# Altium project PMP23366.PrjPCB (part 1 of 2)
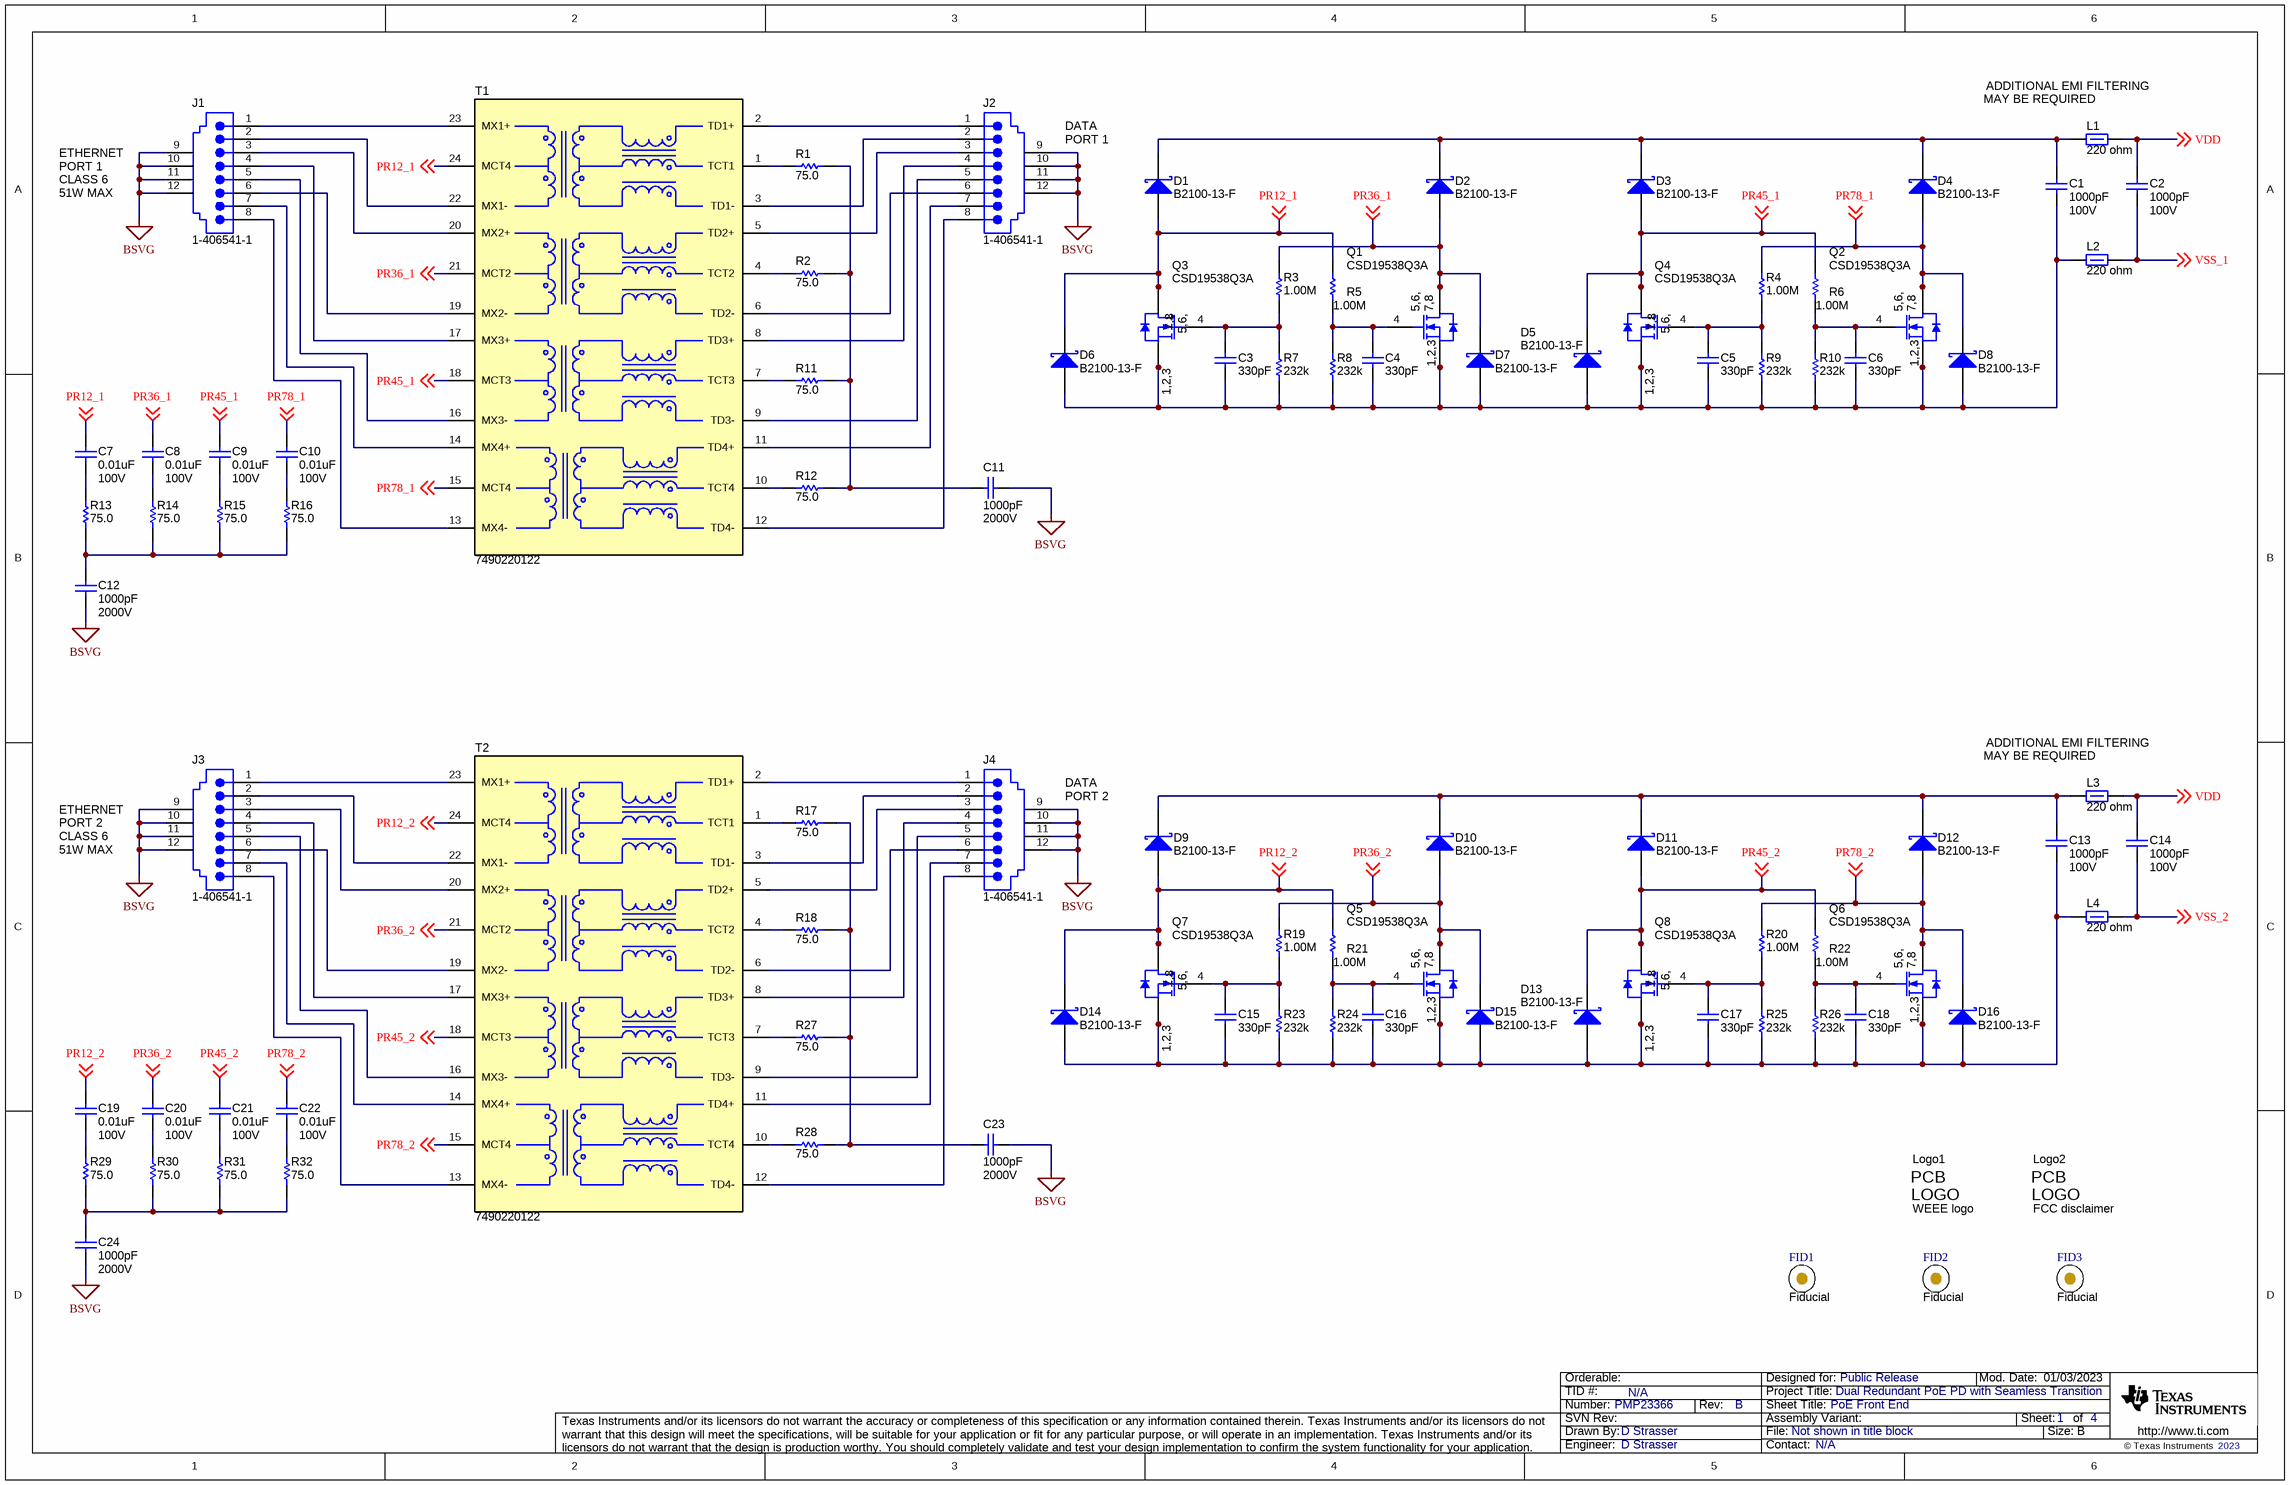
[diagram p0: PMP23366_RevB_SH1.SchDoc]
CopyrightYear: 2023; PCB_Layout: D Strasser; PCB_Rev: B; PRJ_Customer: Public Release; PRJ_Engineer: D Strasser; PRJ_Number: PMP23366; PRJ_Title: Dual Redundant PoE PD with Seamless Transition; SCH_Rev: B; TechSupport: N/A; TID: N/A
4 sheets, 370 parts. Net scope: global (net labels, ports and power ports of the same name join across sheets).
Board file: PMP23366_RevB.PcbDoc
Sheets:
  PMP23366_RevB_SH1.SchDoc
  PMP23366_RevB_SH2.SchDoc
  PMP23366_RevB_SH3.SchDoc
  PMP23366_RevB_SH4.SchDoc

## Sheet PMP23366_RevB_SH1.SchDoc: PoE Front End
size 431 x 279 mm; Date: Not shown in title block; ApprovedBy: Not shown in title block; CheckedBy: Not shown in title block; Author: Not shown in title block; CompanyName: Not shown in title block; DrawnBy: D Strasser; Engineer: Not shown in title block; Organization: Not shown in title block; Address1: Not shown in title block; Address2: Not shown in title block; Address3: Not shown in title block; Address4: Not shown in title block; DocumentNumber: 1; Revision: Use project parameter SCH_Rev; SheetNumber: 1; SheetTotal: 4; PageSetup: Record=PageOptions¦CenterHorizontal=True¦CenterVertical=True¦PrintScale=1.00¦XCorrection=1.00¦YCorrection=1.00¦PrintKind=0¦BorderSize=5000000¦LeftOffset=0¦BottomOffset=0¦Orientation=2¦PaperLength=1000¦PaperWidth=1000¦Scale=100¦PaperSource=15¦PrintQuality=600¦MediaType=1¦DitherType=10¦PaperKind=Letter¦PrintScaleMode=1

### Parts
C1  ValueDisplayed: 1000pF  Value2: 100V  [0603_HV]  (hidden comment: Capacitor)
C2  ValueDisplayed: 1000pF  Value2: 100V  [0603_HV]  (hidden comment: Capacitor)
C3  ValueDisplayed: 330pF  [0603L]  (hidden comment: Capacitor)
C4  ValueDisplayed: 330pF  [0603L]  (hidden comment: Capacitor)
C5  ValueDisplayed: 330pF  [0603L]  (hidden comment: Capacitor)
C6  ValueDisplayed: 330pF  [0603L]  (hidden comment: Capacitor)
C7  ValueDisplayed: 0.01uF  Value2: 100V  [0603L]  (hidden comment: Capacitor)
C8  ValueDisplayed: 0.01uF  Value2: 100V  [0603L]  (hidden comment: Capacitor)
C9  ValueDisplayed: 0.01uF  Value2: 100V  [0603L]  (hidden comment: Capacitor)
C10  ValueDisplayed: 0.01uF  Value2: 100V  [0603L]  (hidden comment: Capacitor)
C11  ValueDisplayed: 1000pF  Value2: 2000V  [1812]  (hidden comment: Capacitor)
C12  ValueDisplayed: 1000pF  Value2: 2000V  [1812]  (hidden comment: Capacitor)
C13  ValueDisplayed: 1000pF  Value2: 100V  [0603_HV]  (hidden comment: Capacitor)
C14  ValueDisplayed: 1000pF  Value2: 100V  [0603_HV]  (hidden comment: Capacitor)
C15  ValueDisplayed: 330pF  [0603L]  (hidden comment: Capacitor)
C16  ValueDisplayed: 330pF  [0603L]  (hidden comment: Capacitor)
C17  ValueDisplayed: 330pF  [0603L]  (hidden comment: Capacitor)
C18  ValueDisplayed: 330pF  [0603L]  (hidden comment: Capacitor)
C19  ValueDisplayed: 0.01uF  Value2: 100V  [0603L]  (hidden comment: Capacitor)
C20  ValueDisplayed: 0.01uF  Value2: 100V  [0603L]  (hidden comment: Capacitor)
C21  ValueDisplayed: 0.01uF  Value2: 100V  [0603L]  (hidden comment: Capacitor)
C22  ValueDisplayed: 0.01uF  Value2: 100V  [0603L]  (hidden comment: Capacitor)
C23  ValueDisplayed: 1000pF  Value2: 2000V  [1812]  (hidden comment: Capacitor)
C24  ValueDisplayed: 1000pF  Value2: 2000V  [1812]  (hidden comment: Capacitor)
D1  B2100-13-F  [SMB]
D2  B2100-13-F  [SMB]
D3  B2100-13-F  [SMB]
D4  B2100-13-F  [SMB]
D5  B2100-13-F  [SMB]
D6  B2100-13-F  [SMB]
D7  B2100-13-F  [SMB]
D8  B2100-13-F  [SMB]
D9  B2100-13-F  [SMB]
D10  B2100-13-F  [SMB]
D11  B2100-13-F  [SMB]
D12  B2100-13-F  [SMB]
D13  B2100-13-F  [SMB]
D14  B2100-13-F  [SMB]
D15  B2100-13-F  [SMB]
D16  B2100-13-F  [SMB]
FID1  Fiducial  [Fiducial10-20]
FID2  Fiducial  [Fiducial10-20]
FID3  Fiducial  [Fiducial10-20]
J1  1-406541-1  [TEC_1-406541-1]
J2  1-406541-1  [TEC_1-406541-1]
J3  1-406541-1  [TEC_1-406541-1]
J4  1-406541-1  [TEC_1-406541-1]
L1  value 220 ohm  [0603_HV]  (hidden comment: Ferrite_Bead)
L2  value 220 ohm  [0603_HV]  (hidden comment: Ferrite_Bead)
L3  value 220 ohm  [0603_HV]  (hidden comment: Ferrite_Bead)
L4  value 220 ohm  [0603_HV]  (hidden comment: Ferrite_Bead)
Logo1  WEEE logo  [WEEE_Minimum]  (no BOM)
Logo2  FCC disclaimer  [FCC_disclaimer]  (no BOM)
Q1  CSD19538Q3A  [DNH0008A_NV]
Q2  CSD19538Q3A  [DNH0008A_NV]
Q3  CSD19538Q3A  [DNH0008A_NV]
Q4  CSD19538Q3A  [DNH0008A_NV]
Q5  CSD19538Q3A  [DNH0008A_NV]
Q6  CSD19538Q3A  [DNH0008A_NV]
Q7  CSD19538Q3A  [DNH0008A_NV]
Q8  CSD19538Q3A  [DNH0008A_NV]
R1  value 75.0  [0603L]  (hidden comment: Resistor)
R2  value 75.0  [0603L]  (hidden comment: Resistor)
R3  ValueDisplayed: 1.00M  [0603L]  (hidden comment: Resistor)
R4  ValueDisplayed: 1.00M  [0603L]  (hidden comment: Resistor)
R5  ValueDisplayed: 1.00M  [0603L]  (hidden comment: Resistor)
R6  ValueDisplayed: 1.00M  [0603L]  (hidden comment: Resistor)
R7  ValueDisplayed: 232k  [0603L]  (hidden comment: Resistor)
R8  ValueDisplayed: 232k  [0603L]  (hidden comment: Resistor)
R9  ValueDisplayed: 232k  [0603L]  (hidden comment: Resistor)
R10  ValueDisplayed: 232k  [0603L]  (hidden comment: Resistor)
R11  value 75.0  [0603L]  (hidden comment: Resistor)
R12  value 75.0  [0603L]  (hidden comment: Resistor)
R13  value 75.0  [0603L]  (hidden comment: Resistor)
R14  value 75.0  [0603L]  (hidden comment: Resistor)
R15  value 75.0  [0603L]  (hidden comment: Resistor)
R16  value 75.0  [0603L]  (hidden comment: Resistor)
R17  value 75.0  [0603L]  (hidden comment: Resistor)
R18  value 75.0  [0603L]  (hidden comment: Resistor)
R19  ValueDisplayed: 1.00M  [0603L]  (hidden comment: Resistor)
R20  ValueDisplayed: 1.00M  [0603L]  (hidden comment: Resistor)
R21  ValueDisplayed: 1.00M  [0603L]  (hidden comment: Resistor)
R22  ValueDisplayed: 1.00M  [0603L]  (hidden comment: Resistor)
R23  ValueDisplayed: 232k  [0603L]  (hidden comment: Resistor)
R24  ValueDisplayed: 232k  [0603L]  (hidden comment: Resistor)
R25  ValueDisplayed: 232k  [0603L]  (hidden comment: Resistor)
R26  ValueDisplayed: 232k  [0603L]  (hidden comment: Resistor)
R27  value 75.0  [0603L]  (hidden comment: Resistor)
R28  value 75.0  [0603L]  (hidden comment: Resistor)
R29  value 75.0  [0603L]  (hidden comment: Resistor)
R30  value 75.0  [0603L]  (hidden comment: Resistor)
R31  value 75.0  [0603L]  (hidden comment: Resistor)
R32  value 75.0  [0603L]  (hidden comment: Resistor)
T1  7490220122  [Wurth_7490220122]
T2  7490220122  [Wurth_7490220122]

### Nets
BSVG: C11.1 C12.2 C23.1 C24.2 J1.9 J1.10 J1.11 J1.12 J2.9 J2.10 J2.11 J2.12 J3.9 J3.10 J3.11 J3.12 J4.9 J4.10 J4.11 J4.12
PR12_1: C7.1 D1.2(A) D6.1(K) Q3.5(D) Q3.6(D) Q3.7(D) Q3.8(D) Q3.9(D) R5.1 T1.24(MCT4) ; off-sheet PR12_1
PR12_2: C19.1 D9.2(A) D14.1(K) Q7.5(D) Q7.6(D) Q7.7(D) Q7.8(D) Q7.9(D) R21.1 T2.24(MCT4) ; off-sheet PR12_2
PR36_1: C8.1 D2.2(A) D7.1(K) Q1.5(D) Q1.6(D) Q1.7(D) Q1.8(D) Q1.9(D) R3.1 T1.21(MCT2) ; off-sheet PR36_1
PR36_2: C20.1 D10.2(A) D15.1(K) Q5.5(D) Q5.6(D) Q5.7(D) Q5.8(D) Q5.9(D) R19.1 T2.21(MCT2) ; off-sheet PR36_2
PR45_1: C9.1 D3.2(A) D5.1(K) Q4.5(D) Q4.6(D) Q4.7(D) Q4.8(D) Q4.9(D) R6.1 T1.18(MCT3) ; off-sheet PR45_1
PR45_2: C21.1 D11.2(A) D13.1(K) Q8.5(D) Q8.6(D) Q8.7(D) Q8.8(D) Q8.9(D) R22.1 T2.18(MCT3) ; off-sheet PR45_2
PR78_1: C10.1 D4.2(A) D8.1(K) Q2.5(D) Q2.6(D) Q2.7(D) Q2.8(D) Q2.9(D) R4.1 T1.15(MCT4) ; off-sheet PR78_1
PR78_2: C22.1 D12.2(A) D16.1(K) Q6.5(D) Q6.6(D) Q6.7(D) Q6.8(D) Q6.9(D) R20.1 T2.15(MCT4) ; off-sheet PR78_2
VDD: C2.1 C14.1 L1.2 L3.2 ; off-sheet VDD
VSS_1: C2.2 L2.2 ; off-sheet VSS_1
VSS_2: C14.2 L4.2 ; off-sheet VSS_2
NetC1_1: C1.1 D1.1(K) D2.1(K) D3.1(K) D4.1(K) L1.1
NetC1_2: C1.2 C3.2 C4.2 C5.2 C6.2 D5.2(A) D6.2(A) D7.2(A) D8.2(A) L2.1 Q1.1(S) Q1.2(S) Q1.3(S) Q2.1(S) Q2.2(S) Q2.3(S) Q3.1(S) Q3.2(S) Q3.3(S) Q4.1(S) Q4.2(S) Q4.3(S) R7.1 R8.1 R9.1 R10.1
NetC3_1: C3.1 Q3.4(G) R3.2 R7.2
NetC4_1: C4.1 Q1.4(G) R5.2 R8.2
NetC5_1: C5.1 Q4.4(G) R4.2 R9.2
NetC6_1: C6.1 Q2.4(G) R6.2 R10.2
NetC7_2: C7.2 R13.2
NetC8_2: C8.2 R14.2
NetC9_2: C9.2 R15.2
NetC10_2: C10.2 R16.2
NetC11_2: C11.2 R1.1 R2.1 R11.1 R12.1
NetC12_1: C12.1 R13.1 R14.1 R15.1 R16.1
NetC13_1: C13.1 D9.1(K) D10.1(K) D11.1(K) D12.1(K) L3.1
NetC13_2: C13.2 C15.2 C16.2 C17.2 C18.2 D13.2(A) D14.2(A) D15.2(A) D16.2(A) L4.1 Q5.1(S) Q5.2(S) Q5.3(S) Q6.1(S) Q6.2(S) Q6.3(S) Q7.1(S) Q7.2(S) Q7.3(S) Q8.1(S) Q8.2(S) Q8.3(S) R23.1 R24.1 R25.1 R26.1
NetC15_1: C15.1 Q7.4(G) R19.2 R23.2
NetC16_1: C16.1 Q5.4(G) R21.2 R24.2
NetC17_1: C17.1 Q8.4(G) R20.2 R25.2
NetC18_1: C18.1 Q6.4(G) R22.2 R26.2
NetC19_2: C19.2 R29.2
NetC20_2: C20.2 R30.2
NetC21_2: C21.2 R31.2
NetC22_2: C22.2 R32.2
NetC23_2: C23.2 R17.1 R18.1 R27.1 R28.1
NetC24_1: C24.1 R29.1 R30.1 R31.1 R32.1
NetJ1_1: J1.1 T1.23(MX1+)
NetJ1_2: J1.2 T1.22(MX1-)
NetJ1_3: J1.3 T1.20(MX2+)
NetJ1_4: J1.4 T1.17(MX3+)
NetJ1_5: J1.5 T1.16(MX3-)
NetJ1_6: J1.6 T1.19(MX2-)
NetJ1_7: J1.7 T1.14(MX4+)
NetJ1_8: J1.8 T1.13(MX4-)
NetJ2_1: J2.1 T1.2(TD1+)
NetJ2_2: J2.2 T1.3(TD1-)
NetJ2_3: J2.3 T1.5(TD2+)
NetJ2_4: J2.4 T1.8(TD3+)
NetJ2_5: J2.5 T1.9(TD3-)
NetJ2_6: J2.6 T1.6(TD2-)
NetJ2_7: J2.7 T1.11(TD4+)
NetJ2_8: J2.8 T1.12(TD4-)
NetJ3_1: J3.1 T2.23(MX1+)
NetJ3_2: J3.2 T2.22(MX1-)
NetJ3_3: J3.3 T2.20(MX2+)
NetJ3_4: J3.4 T2.17(MX3+)
NetJ3_5: J3.5 T2.16(MX3-)
NetJ3_6: J3.6 T2.19(MX2-)
NetJ3_7: J3.7 T2.14(MX4+)
NetJ3_8: J3.8 T2.13(MX4-)
NetJ4_1: J4.1 T2.2(TD1+)
NetJ4_2: J4.2 T2.3(TD1-)
NetJ4_3: J4.3 T2.5(TD2+)
NetJ4_4: J4.4 T2.8(TD3+)
NetJ4_5: J4.5 T2.9(TD3-)
NetJ4_6: J4.6 T2.6(TD2-)
NetJ4_7: J4.7 T2.11(TD4+)
NetJ4_8: J4.8 T2.12(TD4-)
NetR1_2: R1.2 T1.1(TCT1)
NetR2_2: R2.2 T1.4(TCT2)
NetR11_2: R11.2 T1.7(TCT3)
NetR12_2: R12.2 T1.10(TCT4)
NetR17_2: R17.2 T2.1(TCT1)
NetR18_2: R18.2 T2.4(TCT2)
NetR27_2: R27.2 T2.7(TCT3)
NetR28_2: R28.2 T2.10(TCT4)

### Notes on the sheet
- (near L1) MAY BE REQUIRED
- (near L1) ADDITIONAL EMI FILTERING
- ETHERNET
- PORT 1
- (near J2) DATA
- (near J2) PORT 1
- 51W MAX
- CLASS 6
- (near L3) MAY BE REQUIRED
- (near L3) ADDITIONAL EMI FILTERING
- PORT 2
- (near J4) DATA
- (near J4) PORT 2

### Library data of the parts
C1 C2 C13 C14 = CMP-0007053-4: CAP, CERM, 1000 pF, 100 V, +/- 10%, X7R, 0603; PartNumber: C1608X7R2A102K080AA; Manufacturer: TDK; Polarized: N; Value: 1000pF; U/M: EA; Cap_F: 1nF; Value1: Unknown; TaMin_C: -55°C; TaMax_C: 125°C; Cap_Case: 0603; SizeArea_mm2: 1.28; SizeAreaWB_mm2: 4.68; SizeX_mm: 1.6; SizeY_mm: 0.8; SizeZ_mm: 1; AEC Category: Q200
C3-C6 C15-C18 = CMP-0007209-4: CAP, CERM, 330 pF, 50 V, +/- 5%, C0G/NP0, 0603; PartNumber: GRM1885C1H331JA01D; Manufacturer: MuRata; Polarized: N; Value: 330pF; U/M: EA; Value1: Unknown; VDC_V: 50V; TaMin_C: -55°C; TaMax_C: 125°C; Cap_Case: 0603; SizeArea_mm2: 1.28; SizeAreaWB_mm2: 4.68; SizeX_mm: 1.6; SizeY_mm: 0.8; SizeZ_mm: 1; AEC Category: Q200
C7-C10 C19-C22 = CMP-0007468-5: CAP, CERM, 0.01 uF, 100 V, +/- 10%, X7R, 0603; PartNumber: GRM188R72A103KA01D; Manufacturer: MuRata; Polarized: N; Value: 0.01uF; U/M: EA; Cap_F: 10nF; Value1: Unknown; TaMin_C: -55°C; TaMax_C: 125°C; Cap_Case: 0603; SizeArea_mm2: 1.28; SizeAreaWB_mm2: 4.68; SizeX_mm: 1.6; SizeY_mm: 0.8; SizeZ_mm: 1; AEC Category: Q200
C11 C12 C23 C24 = CMP-0009438-2: CAP, CERM, 1000 pF, 2000 V, +/- 10%, X7R, 1812; PartNumber: GR443QR73D102KW01L; Manufacturer: MuRata; Polarized: N; Value: 1000pF; U/M: EA; Cap_F: 1nF; Value1: Unknown; VDC_V: 2kV; TaMin_C: -55°C; TaMax_C: 125°C; SizeArea_mm2: 14.4; SizeAreaWB_mm2: 23.1; SizeX_mm: 4.5; SizeY_mm: 3.2; SizeZ_mm: 1.35; AEC Category: Q200
D1-D16 = CMP-0028397-2: Diode, Schottky, 100 V, 2 A, SMB; Manufacturer: Diodes Inc.; Value2: 0.79V; Value1: 2A; SizeArea_mm2: 21.336; Value: 100V; Green_REACh: Passed; Green_Lifecycle: Active; Vf_V: 790mV; SizeY_mm: 3.81; AEC Category: Q101; SizeZ_mm: 2.6; TJmax_C: 150°C; RJC_CperW: 15; SizeAreaWB_mm2: 44.156; SizeX_mm: 5.6
FID1-FID3 = CMP-0077181-1: Fiducial mark.  There is nothing to buy or mount.
J1-J4 = CMP-0054918-1: RJ45, No LED, tab up, R/A, TH; Manufacturer: TE Connectivity; CNHeader: FALSE; ContactFinish: Gold; CT: TRUE; Green_Lifecycle: Active; Green_REACh: Passed
L1-L4 = CMP-0003425-2: Ferrite Bead, 220 ohm @ 100 MHz, 2.2 A, 0603; PartNumber: MPZ1608S221A; Manufacturer: TDK; Imax_A: 2.2A; DCR_ohm: 0.05; Value1: 0.05 ohm; ZTyp@100MHz_Ohm: 220; SizeArea_mm2: 1.28; SizeAreaWB_mm2: 4.68; SizeX_mm: 1.6; SizeY_mm: 0.8; SizeZ_mm: 1
Logo1 = CMP-0074769-3: Manufacturer: Texas Instruments; CompType: IC; AEC Category: Q200
Logo2 = CMP-0074847-1: FCC_disclaimer
Q1-Q8 = CMP-0000969-3: MOSFET, N-CH, 100 V, 5 A, DNH0008A (VSONP-8); Alternate Manufacturer: None; Manufacturer: Texas Instruments; SizeZ_mm: 0.9; ChType: N; Value2: 7.2 nC; VdsMax_V: 100V; SizeX_mm: 3.3; SizeAreaWB_mm2: 18.49; Vgs_V: 20V; QgTyp_nC: 7.2; Value: 100V; SizeArea_mm2: 10.89; AEC Category: Q101; IdsMax_A: 5A; ChMode: Enhancement
R1 R2 R11-R18 R27-R32 = CMP-0022590-4: RES, 75.0, 1%, 0.1 W, AEC-Q200 Grade 0, 0603; PartNumber: CRCW060375R0FKEA; Manufacturer: Vishay-Dale; Res_ohm: 75; Value_Code: 75R0; Power_W: 100mW; Value2: 0.1W; VDC_V: 75V; TempCo: 100 ppm/C; EIA_Code: E96; AEC Category: Q200; AEC Grade: 0; AEC Qualified: Y; SizeArea_mm2: 1.28; SizeX_mm: 1.6; SizeY_mm: 0.8; SizeZ_mm: 1
R3-R6 R19-R22 = CMP-0022138-4: RES, 1.00 M, 1%, 0.1 W, AEC-Q200 Grade 0, 0603; PartNumber: CRCW06031M00FKEA; Manufacturer: Vishay-Dale; Value: 1.00Meg; Res_ohm: 1M; Value_Code: 1M00; Power_W: 100mW; Value2: 0.1W; VDC_V: 75V; TempCo: 100 ppm/C; EIA_Code: E96; SizeArea_mm2: 1.28; SizeX_mm: 1.6; SizeY_mm: 0.8; SizeZ_mm: 1; AEC Category: Q200; AEC Qualified: Y; AEC Grade: 0
R7-R10 R23-R26 = CMP-0022224-4: RES, 232 k, 1%, 0.1 W, AEC-Q200 Grade 0, 0603; PartNumber: CRCW0603232KFKEA; Manufacturer: Vishay-Dale; Value: 232k; Power_W: 100mW; Value2: 0.1W; VDC_V: 75V; TempCo: 100 ppm/C; EIA_Code: E96; SizeArea_mm2: 1.28; SizeX_mm: 1.6; SizeY_mm: 0.8; SizeZ_mm: 1; AEC Category: Q200; AEC Qualified: Y; AEC Grade: 0
T1 T2 = CMP-0030597-1: Transformer, 350 uH, SMT; Manufacturer: Wurth Elektronik; Value: 350uH; Lp: 350; Ind_H: 350µH

## Sheet PMP23366_RevB_SH2.SchDoc: PoE PDs and Seamless Transition
size 431 x 279 mm; Date: Not shown in title block; ApprovedBy: Not shown in title block; CheckedBy: Not shown in title block; Author: Not shown in title block; CompanyName: Not shown in title block; DrawnBy: D Strassser; Engineer: Not shown in title block; Organization: Not shown in title block; Address1: Not shown in title block; Address2: Not shown in title block; Address3: Not shown in title block; Address4: Not shown in title block; DocumentNumber: 2; Revision: Use project parameter SCH_Rev; SheetNumber: 2; SheetTotal: 4; PageSetup: Record=PageOptions¦CenterHorizontal=True¦CenterVertical=True¦PrintScale=1.00¦XCorrection=1.00¦YCorrection=1.00¦PrintKind=0¦BorderSize=5000000¦LeftOffset=0¦BottomOffset=0¦Orientation=2¦PaperLength=1000¦PaperWidth=1000¦Scale=100¦PaperSource=15¦PrintQuality=600¦MediaType=1¦DitherType=10¦PaperKind=Letter¦PrintScaleMode=1
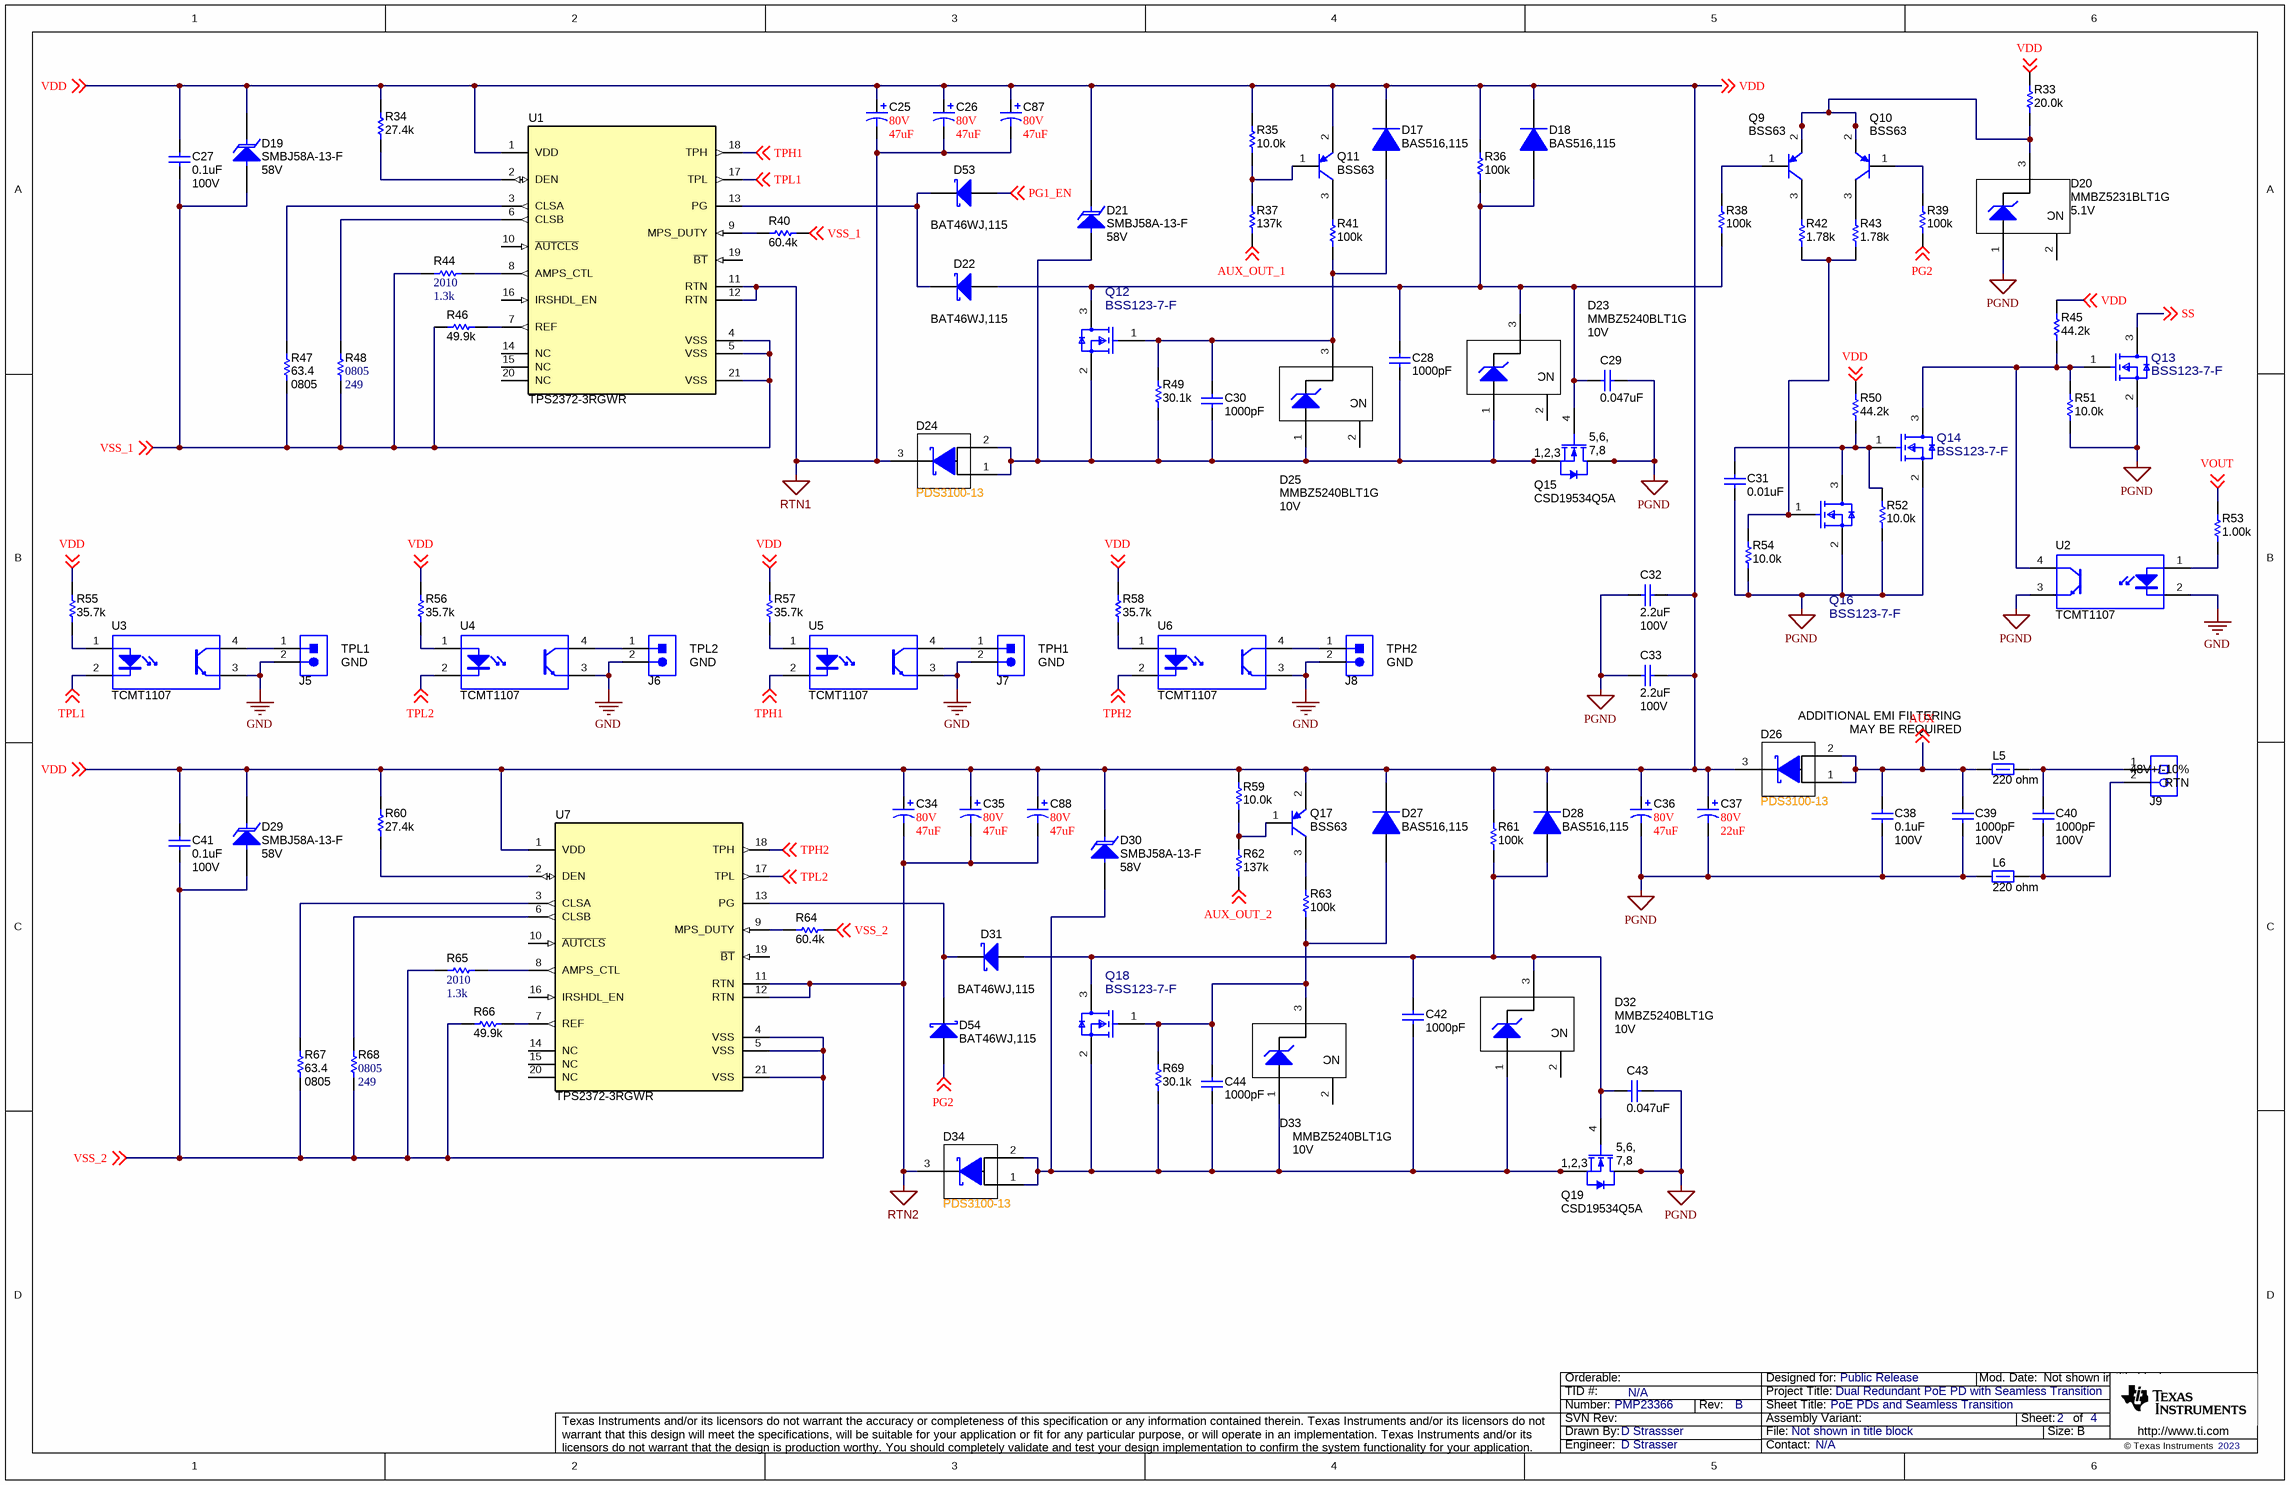
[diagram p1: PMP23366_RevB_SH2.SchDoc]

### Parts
C25  VDC_V: 80V  ValueDisplayed: 47uF  [SM_RADIAL_10BMM]  (hidden comment: EEHZC1K470P)
C26  VDC_V: 80V  ValueDisplayed: 47uF  [SM_RADIAL_10BMM]  (hidden comment: EEHZC1K470P)
C27  ValueDisplayed: 0.1uF  Value2: 100V  [0805_HV1]  (hidden comment: Capacitor)
C28  ValueDisplayed: 1000pF  [0603L]  (hidden comment: Capacitor)
C29  ValueDisplayed: 0.047uF  [0805L]  (hidden comment: Capacitor)
C30  ValueDisplayed: 1000pF  [0603L]  (hidden comment: Capacitor)
C31  ValueDisplayed: 0.01uF  [0603L]  (hidden comment: Capacitor)
C32  ValueDisplayed: 2.2uF  Value2: 100V  [1210_270]  (hidden comment: Capacitor)
C33  ValueDisplayed: 2.2uF  Value2: 100V  [1210_270]  (hidden comment: Capacitor)
C34  VDC_V: 80V  ValueDisplayed: 47uF  [SM_RADIAL_10BMM]  (hidden comment: EEHZC1K470P)
C35  VDC_V: 80V  ValueDisplayed: 47uF  [SM_RADIAL_10BMM]  (hidden comment: EEHZC1K470P)
C36  VDC_V: 80V  ValueDisplayed: 47uF  [SM_RADIAL_10BMM]  (hidden comment: EEHZC1K470P)
C37  VDC_V: 80V  ValueDisplayed: 22uF  [SM_RADIAL_8MM]  (hidden comment: EEHZC1K220P)
C38  ValueDisplayed: 0.1uF  Value2: 100V  [0805_HV1]  (hidden comment: Capacitor)
C39  ValueDisplayed: 1000pF  Value2: 100V  [0603_HV]  (hidden comment: Capacitor)
C40  ValueDisplayed: 1000pF  Value2: 100V  [0603_HV]  (hidden comment: Capacitor)
C41  ValueDisplayed: 0.1uF  Value2: 100V  [0805_HV1]  (hidden comment: Capacitor)
C42  ValueDisplayed: 1000pF  [0603L]  (hidden comment: Capacitor)
C43  ValueDisplayed: 0.047uF  [0805L]  (hidden comment: Capacitor)
C44  ValueDisplayed: 1000pF  [0603L]  (hidden comment: Capacitor)
C87  VDC_V: 80V  ValueDisplayed: 47uF  [SM_RADIAL_10BMM]  (hidden comment: EEHZC1K470P)
C88  VDC_V: 80V  ValueDisplayed: 47uF  [SM_RADIAL_10BMM]  (hidden comment: EEHZC1K470P)
D17  BAS516,115  [SOD-523]
D18  BAS516,115  [SOD-523]
D19  SMBJ58A-13-F  value 58V  [SMB]
D20  MMBZ5231BLT1G  value 5.1V  [SOT-23L]
D21  SMBJ58A-13-F  value 58V  [SMB]
D22  BAT46WJ,115  [SOD-323F]
D23  MMBZ5240BLT1G  value 10V  [SOT-23L]
D24  PDS3100-13  [POWERDI5]
D25  MMBZ5240BLT1G  value 10V  [SOT-23L]
D26  PDS3100-13  [POWERDI5]
D27  BAS516,115  [SOD-523]
D28  BAS516,115  [SOD-523]
D29  SMBJ58A-13-F  value 58V  [SMB]
D30  SMBJ58A-13-F  value 58V  [SMB]
D31  BAT46WJ,115  [SOD-323F]
D32  MMBZ5240BLT1G  value 10V  [SOT-23L]
D33  MMBZ5240BLT1G  value 10V  [SOT-23L]
D34  PDS3100-13  [POWERDI5]
D53  BAT46WJ,115  [SOD-323F]
D54  BAT46WJ,115  [SOD-323F]
J5  PEC02SAAN  [CONN_PEC02SAAN]  (value not drawn)
J6  PEC02SAAN  [CONN_PEC02SAAN]  (value not drawn)
J7  PEC02SAAN  [CONN_PEC02SAAN]  (value not drawn)
J8  PEC02SAAN  [CONN_PEC02SAAN]  (value not drawn)
J9  ED555/2DS  [TERM_BLK_ED555-2DS]  (value not drawn)
L5  value 220 ohm  [0603]  (hidden comment: Ferrite_Bead)
L6  value 220 ohm  [0603]  (hidden comment: Ferrite_Bead)
Q9  BSS63  [SOT-23L]
Q10  BSS63  [SOT-23L]
Q11  BSS63  [SOT-23L]
Q12  BSS123-7-F  [FP-BSS123-7-F_SOT23-MFG]
Q13  BSS123-7-F  [FP-BSS123-7-F_SOT23-MFG]
Q14  BSS123-7-F  [FP-BSS123-7-F_SOT23-MFG]
Q15  CSD19534Q5A  [DQJ0008A]
Q16  BSS123-7-F  [FP-BSS123-7-F_SOT23-MFG]
Q17  BSS63  [SOT-23L]
Q18  BSS123-7-F  [FP-BSS123-7-F_SOT23-MFG]
Q19  CSD19534Q5A  [DQJ0008A]
R33  ValueDisplayed: 20.0k  [0603L]  (hidden comment: Resistor)
R34  ValueDisplayed: 27.4k  [0603L]  (hidden comment: Resistor)
R35  ValueDisplayed: 10.0k  [0603L]  (hidden comment: Resistor)
R36  ValueDisplayed: 100k  [0603L]  (hidden comment: Resistor)
R37  ValueDisplayed: 137k  [0603L]  (hidden comment: Resistor)
R38  ValueDisplayed: 100k  [0603L]  (hidden comment: Resistor)
R39  ValueDisplayed: 100k  [0603L]  (hidden comment: Resistor)
R40  Res_ohm: 60.4k  [0603L]  (hidden comment: CRCW060360K4FKEA)
R41  ValueDisplayed: 100k  [0603L]  (hidden comment: Resistor)
R42  ValueDisplayed: 1.78k  [0603L]  (hidden comment: Resistor)
R43  ValueDisplayed: 1.78k  [0603L]  (hidden comment: Resistor)
R44  PackageReference: 2010  ValueDisplayed: 1.3k  [2010L]  (hidden comment: CRCW20101K30JNEF)
R45  ValueDisplayed: 44.2k  [0603L]  (hidden comment: Resistor)
R46  ValueDisplayed: 49.9k  [0603L]  (hidden comment: Resistor)
R47  ValueDisplayed: 63.4  PackageReference: 0805  [0805_HV1]  (hidden comment: Resistor)
R48  PackageReference: 0805  ValueDisplayed: 249  [0805_HV1]  (hidden comment: CRCW0805249RFKEA)
R49  ValueDisplayed: 30.1k  [0603L]  (hidden comment: Resistor)
R50  ValueDisplayed: 44.2k  [0603L]  (hidden comment: Resistor)
R51  ValueDisplayed: 10.0k  [0603L]  (hidden comment: Resistor)
R52  ValueDisplayed: 10.0k  [0603L]  (hidden comment: Resistor)
R53  ValueDisplayed: 1.00k  [0603L]  (hidden comment: Resistor)
R54  ValueDisplayed: 10.0k  [0603L]  (hidden comment: Resistor)
R55  Res_ohm: 35.7k  [0603L]  (hidden comment: RC0603FR-0735K7L)
R56  Res_ohm: 35.7k  [0603L]  (hidden comment: RC0603FR-0735K7L)
R57  Res_ohm: 35.7k  [0603L]  (hidden comment: RC0603FR-0735K7L)
R58  Res_ohm: 35.7k  [0603L]  (hidden comment: RC0603FR-0735K7L)
R59  ValueDisplayed: 10.0k  [0603L]  (hidden comment: CRCW060310K0FKEA)
R60  ValueDisplayed: 27.4k  [0603L]  (hidden comment: Resistor)
R61  ValueDisplayed: 100k  [0603L]  (hidden comment: Resistor)
R62  ValueDisplayed: 137k  [0603L]  (hidden comment: Resistor)
R63  ValueDisplayed: 100k  [0603L]  (hidden comment: Resistor)
R64  ValueDisplayed: 60.4k  [0603L]  (hidden comment: CRCW060360K4FKEA)
R65  PackageReference: 2010  ValueDisplayed: 1.3k  [2010L]  (hidden comment: CRCW20101K30JNEF)
R66  ValueDisplayed: 49.9k  [0603L]  (hidden comment: Resistor)
R67  ValueDisplayed: 63.4  PackageReference: 0805  [0805_HV1]  (hidden comment: Resistor)
R68  PackageReference: 0805  ValueDisplayed: 249  [0805_HV1]  (hidden comment: CRCW0805249RFKEA)
R69  ValueDisplayed: 30.1k  [0603L]  (hidden comment: Resistor)
U1  TPS2372-3RGWR  [RGW0020B]
U2  TCMT1107  [SOP-4]
U3  TCMT1107  [SOP-4]
U4  TCMT1107  [SOP-4]
U5  TCMT1107  [SOP-4]
U6  TCMT1107  [SOP-4]
U7  TPS2372-3RGWR  [RGW0020B]

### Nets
GND: J5.2 J6.2 J7.2 J8.2 U2.2(K) U3.3(E) U4.3(E) U5.3(E) U6.3(E)
PGND: C29.1 C31.2 C32.1 C33.1 C36.2(-) C37.2(-) C38.2 C39.2 C43.1 D20.1(A) L6.2 Q13.2(S) Q14.2(S) Q15.5(D) Q15.6(D) Q15.7(D) Q15.8(D) Q15.9(D) Q16.2(S) Q19.5(D) Q19.6(D) Q19.7(D) Q19.8(D) Q19.9(D) R51.1 R52.1 R54.1 U2.3(E)
RTN1: C25.2(-) C26.2(-) C87.2(-) D24.3(K) U1.11(RTN) U1.12(RTN)
RTN2: C34.2(-) C35.2(-) C88.2(-) D34.3(K) U7.11(RTN) U7.12(RTN)
AUX: C38.1 C39.1 D26.1(A) D26.2(A) L5.2 ; off-sheet AUX
AUX_OUT_1: R37.2 ; off-sheet AUX_OUT_1
AUX_OUT_2: R62.2 ; off-sheet AUX_OUT_2
PG1_EN: D53.2(A) ; off-sheet PG1_EN
PG2: D54.2(A) R39.1 ; off-sheet PG2
SS: Q13.3(D) ; off-sheet SS
TPH1: U1.18(TPH) U5.2(K) ; off-sheet TPH1
TPH2: U6.2(K) U7.18(TPH) ; off-sheet TPH2
TPL1: U1.17(TPL) U3.2(K) ; off-sheet TPL1
TPL2: U4.2(K) U7.17(TPL) ; off-sheet TPL2
VDD: C25.1(+) C26.1(+) C27.2 C32.2 C33.2 C34.1(+) C35.1(+) C36.1(+) C37.1(+) C41.2 C87.1(+) C88.1(+) D17.1(K) D18.1(K) D19.1(K) D21.1(K) D26.3(K) D27.1(K) D28.1(K) D29.1(K) D30.1(K) Q11.2(E) Q17.2(E) R33.2 R34.2 R35.2 R36.2 R45.2 R50.1 R55.1 R56.1 R57.1 R58.1 R59.2 R60.2 R61.2 U1.1(VDD) U7.1(VDD) ; off-sheet VDD
VOUT: R53.2 ; off-sheet VOUT
VSS_1: C27.1 D19.2(A) R40.2 R44.2 R46.1 R47.1 R48.1 U1.4(VSS) U1.5(VSS) U1.21(VSS) ; off-sheet VSS_1
VSS_2: C41.1 D29.2(A) R64.2 R65.2 R66.1 R67.1 R68.1 U7.4(VSS) U7.5(VSS) U7.21(VSS) ; off-sheet VSS_2
NetC28_1: C28.1 C29.2 D18.2(A) D22.2(A) D23.3(K) Q12.3(D) Q15.4(G) R36.1 R38.1
NetC28_2: C28.2 C30.2 D21.2(A) D23.1(A) D24.1(A) D24.2(A) D25.1(A) Q12.2(S) Q15.1(S) Q15.2(S) Q15.3(S) R49.1
NetC30_1: C30.1 D17.2(A) D25.3(K) Q12.1(G) R41.1 R49.2
NetC31_1: C31.1 Q14.1(G) Q16.3(D) R50.2 R52.2
NetC40_1: C40.1 J9.1 L5.1
NetC40_2: C40.2 J9.2 L6.1
NetC42_1: C42.1 C43.2 D28.2(A) D31.2(A) D32.3(K) Q18.3(D) Q19.4(G) R61.1
NetC42_2: C42.2 C44.2 D30.2(A) D32.1(A) D33.1(A) D34.1(A) D34.2(A) Q18.2(S) Q19.1(S) Q19.2(S) Q19.3(S) R69.1
NetC44_1: C44.1 D27.2(A) D33.3(K) Q18.1(G) R63.1 R69.2
NetD20_3: D20.3(K) Q9.2(E) Q10.2(E) R33.1
NetD22_1: D22.1(K) D53.1(K) U1.13(PG)
NetD31_1: D31.1(K) D54.1(K) U7.13(PG)
NetJ5_1: J5.1 U3.4(C)
NetJ6_1: J6.1 U4.4(C)
NetJ7_1: J7.1 U5.4(C)
NetJ8_1: J8.1 U6.4(C)
NetQ9_1: Q9.1(B) R38.2
NetQ9_3: Q9.3(C) R42.1
NetQ10_1: Q10.1(B) R39.2
NetQ10_3: Q10.3(C) R43.2
NetQ11_1: Q11.1(B) R35.1 R37.1
NetQ11_3: Q11.3(C) R41.2
NetQ13_1: Q13.1(G) Q14.3(D) R45.1 R51.2 U2.4(C)
NetQ16_1: Q16.1(G) R42.2 R43.1 R54.2
NetQ17_1: Q17.1(B) R59.1 R62.1
NetQ17_3: Q17.3(C) R63.2
NetR34_1: R34.1 U1.2(DEN)
NetR40_1: R40.1 U1.9(MPS_DUTY)
NetR44_1: R44.1 U1.8(AMPS_CTL)
NetR46_2: R46.2 U1.7(REF)
NetR47_2: R47.2 U1.3(CLSA)
NetR48_2: R48.2 U1.6(CLSB)
NetR53_1: R53.1 U2.1(A)
NetR55_2: R55.2 U3.1(A)
NetR56_2: R56.2 U4.1(A)
NetR57_2: R57.2 U5.1(A)
NetR58_2: R58.2 U6.1(A)
NetR60_1: R60.1 U7.2(DEN)
NetR64_1: R64.1 U7.9(MPS_DUTY)
NetR65_1: R65.1 U7.8(AMPS_CTL)
NetR66_2: R66.2 U7.7(REF)
NetR67_2: R67.2 U7.3(CLSA)
NetR68_2: R68.2 U7.6(CLSB)

Not connected (* = marked no-connect by the designer): D20 2(NC); D23 2(NC); D25 2(NC); D32 2(NC); D33 2(NC); U1 10(~{AUTCLS}) 14(NC) 15(NC) 16(IRSHDL_EN) 19(~{BT}) 20(NC); U7 10(~{AUTCLS}) 14(NC) 15(NC) 16(IRSHDL_EN) 19(~{BT}) 20(NC)

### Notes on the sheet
- TPL1
- (near J5) GND
- TPL2
- (near J6) GND
- TPH1
- (near J7) GND
- (near J8) TPH2
- (near J8) GND
- ADDITIONAL EMI FILTERING
- (near L5) MAY BE REQUIRED
- (near J9) 48V+/-10%
- (near J9) RTN

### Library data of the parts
C25 C26 C34-C36 C87 C88 = CMP-0012603-3: CAP, Polymer Hybrid, 47 uF, 80 V, +/- 20%, 36 milliohm, 10x10 SMD; Manufacturer: Panasonic; TaMin_C: -55°C; ESR_ohm: 30; Polarized: Y; SizeAreaWB_mm2: 159.9; Value1: 36 ohm; Value: 47uF; TaMax_C: 125°C; SizeZ_mm: 10.2; SizeX_mm: 11; SizeY_mm: 10.3; SizeArea_mm2: 113.3; CompType: Capacitor; Cap_F: 47µF; IRMS_A: 1.36A; AEC Category: Q200
C27 C38 C41 = CMP-0007886-2: CAP, CERM, 0.1 uF, 100 V, +/- 10%, X7R, 0805; PartNumber: C2012X7R2A104K125AA; Manufacturer: TDK; Polarized: N; Value: 0.1uF; U/M: EA; Cap_F: 100nF; ESR_ohm: 0.020726; Value1: 0.020726 ohm; IRMS_A: 1.456A; TaMin_C: -55°C; TaMax_C: 125°C; Cap_Case: 0805; SizeArea_mm2: 2.5; SizeAreaWB_mm2: 6.75; SizeX_mm: 2; SizeY_mm: 1.25; SizeZ_mm: 1.45; AEC Category: Q200
C28 C30 C42 C44 = CMP-0007432-5: CAP, CERM, 1000 pF, 50 V, +/- 10%, X7R, 0603; PartNumber: GRM188R71H102KA01D; Manufacturer: MuRata; Polarized: N; Value: 1000pF; U/M: EA; Cap_F: 1nF; Value1: Unknown; VDC_V: 50V; TaMin_C: -55°C; TaMax_C: 125°C; Cap_Case: 0603; SizeArea_mm2: 1.28; SizeAreaWB_mm2: 4.68; SizeX_mm: 1.6; SizeY_mm: 0.8; SizeZ_mm: 1; AEC Category: Q200
C29 C43 = CMP-0007887-2: CAP, CERM, 0.047 uF, 100 V, +/- 10%, X7R, 0805; PartNumber: C2012X7R2A473K125AA; Manufacturer: TDK; Polarized: N; U/M: EA; Cap_F: 47nF; ESR_ohm: 0.049089; Value1: 0.049089 ohm; VDC_V: 100V; IRMS_A: 9.63171dA; TaMin_C: -55°C; TaMax_C: 125°C; Cap_Case: 0805; SizeArea_mm2: 2.5; SizeAreaWB_mm2: 6.75; SizeX_mm: 2; SizeY_mm: 1.25; SizeZ_mm: 1.45; AEC Category: Q200
C31 = CMP-0007043-4: CAP, CERM, 0.01 uF, 50 V, +/- 10%, X7R, 0603; PartNumber: C1608X7R1H103K080AA; Manufacturer: TDK; Polarized: N; Value: 0.01uF; U/M: EA; Cap_F: 10nF; ESR_ohm: 0.0539; Value1: 0.0539 ohm; VDC_V: 50V; TaMin_C: -55°C; TaMax_C: 125°C; Cap_Case: 0603; SizeArea_mm2: 1.28; SizeAreaWB_mm2: 4.68; SizeX_mm: 1.6; SizeY_mm: 0.8; SizeZ_mm: 1; AEC Category: Q200
C32 C33 = CMP-0009232-2: CAP, CERM, 2.2 uF, 100 V, +/- 10%, X7R, 1210; PartNumber: GRM32ER72A225KA35L; Manufacturer: MuRata; Polarized: N; Value: 2.2uF; U/M: EA; Cap_F: 2.2µF; ESR_ohm: 7m; Value1: 0.007 ohm; IRMS_A: 4.4A; TaMin_C: -55°C; TaMax_C: 125°C; Cap_Case: 1210; SizeArea_mm2: 8; SizeAreaWB_mm2: 14.7; SizeX_mm: 3.2; SizeY_mm: 2.5; SizeZ_mm: 2.7; AEC Category: Q200
C37 = CMP-0012602-3: CAP, Polymer Hybrid, 22 uF, 80 V, +/- 20%, 45 milliohm, 8x10 SMD; Manufacturer: Panasonic; TaMin_C: -55°C; ESR_ohm: 40; Polarized: Y; SizeAreaWB_mm2: 113.3; Value1: 45 ohm; Value: 22uF; TaMax_C: 125°C; SizeZ_mm: 10.2; SizeX_mm: 9; SizeY_mm: 8.3; SizeArea_mm2: 74.7; CompType: Capacitor; Cap_F: 22µF; IRMS_A: 1.1A; AEC Category: Q200
C39 C40 = CMP-0007053-4: as C1 on sheet PMP23366_RevB_SH1
D17 D18 D27 D28 = CMP-0076979-3: Diode, Switching, 100 V, 0.25 A, SOD-523; Manufacturer: Nexperia; Value: 100V; SizeAreaWB_mm2: 5.13; Vf_V: 1.25V; SizeArea_mm2: 1.53; SizeY_mm: 0.9; Green_Lifecycle: Not Set; AEC Category: Q101; SizeX_mm: 1.7; Green_REACh: Incomplete; Io_A: 250mA; TJmax_C: 150°C; SizeZ_mm: 0.65; Value1: 0.25A
D19 D21 D29 D30 = CMP-0005583-3: Diode, TVS, Uni, 58 V, 93.6 Vc, SMB; Manufacturer: Diodes Inc.; Vbr_Max: 74.6V; AEC Category: Q101; Ppk: 600W; Vbr_Min: 64.4V; SizeX_mm: 5.6; SizeZ_mm: 2.6; SizeY_mm: 3.81; Ipp: 6.4A; Vc: 93.6V; SizeAreaWB_mm2: 44.156; SizeArea_mm2: 21.336
D20 = CMP-0005999-3: Diode, Zener, 5.1 V, 225 mW, SOT-23; Manufacturer: ON Semiconductor; SizeZ_mm: 1.1; SizeAreaWB_mm2: 14; Power_W: 225mW; SizeY_mm: 3; SizeArea_mm2: 7.5; RJA_CperW: 556; SizeX_mm: 2.5; AEC Category: Q101; Value1: 0.225W
D22 D31 D53 D54 = CMP-0076946-2: Diode, Schottky, 100 V, 0.25 A, SOD-323F; Manufacturer: Nexperia; SizeAreaWB_mm2: 7.875; Value2: 0.85V; SizeX_mm: 2.5; Green_REACh: Incomplete; SizeArea_mm2: 3.125; Vf_V: 850mV; Green_Lifecycle: Not Set; Vr_V: 100V; TJmax_C: 150°C; Value1: 0.25A; Io_A: 250mA; SizeZ_mm: 0.8; Value: 100V; AEC Category: Q101; SizeY_mm: 1.25
D23 D25 D32 D33 = CMP-0005949-3: Diode, Zener, 10 V, 225 mW, SOT-23; Manufacturer: ON Semiconductor; SizeAreaWB_mm2: 14; RJA_CperW: 556; SizeArea_mm2: 7.5; SizeY_mm: 3; Value1: 0.225W; SizeZ_mm: 1.1; AEC Category: Q101; SizeX_mm: 2.5; Power_W: 225mW
D24 D26 D34 = CMP-0028754-2: Diode, Schottky, 100 V, 3 A, PowerDI5; Manufacturer: Diodes Inc.; Vr_V: 100V; Vf_V: 760mV; Green_Lifecycle: Active; SizeX_mm: 6.4; TJmax_C: 150°C; SizeAreaWB_mm2: 49.56; SizeZ_mm: 1.05; Io_A: 3A; SizeArea_mm2: 24.96; AEC Qualified: Y; Value: 100V; SizeY_mm: 3.9; Value2: 0.76V; Green_REACh: Passed
J5-J8 = CMP-0002337-1: Header, 100mil, 2x1, Tin, TH; Manufacturer: Sullins Connector Solutions; Cert_UL: Y; CNHeader: TRUE; CT: FALSE; Current_A: 3A; Gender: Male; Green_Lifecycle: Not Set; Green_REACh: Incomplete; Pitch_mm: 2.54; Row_Count: 1; Shrouded: N; Voltage_V: 1.8kV
J9 = CMP-0074913-1: Terminal Block, 3.5mm Pitch, 2x1, TH; Manufacturer: On-Shore Technology; Cert_CULUS: Y; CNHeader: False; ContactFinish: Brass; CT: True; Current_A: 6A; Gender: Female; Green_Lifecycle: Active; Green_REACh: Passed; Pitch_mm: 3.5; Row_Count: 1; Shrouded: N; Voltage_V: 150V
L5 L6 = CMP-0003425-2: as L1 on sheet PMP23366_RevB_SH1
Q9-Q11 Q17 = CMP-0000366-2: Transistor, PNP, 100 V, 0.2 A, SOT-23; Manufacturer: Fairchild Semiconductor; TaMax_C: 150°C; Value1: 0.2 A; Vcesat1_V: 250mV; SizeX_mm: 2.5; SizeY_mm: 3; TaMin_C: -55°C; IcRated_A: 200mA; CompType: BJT; SizeZ_mm: 1.1; AEC Qualified: N; Value: 100 V; SizeArea_mm2: 7.5; NPN: 0; Vceo_V: 100V; PNP: 1; AEC Category: Q101; SizeAreaWB_mm2: 14; U/M: EA
Q12-Q14 Q16 Q18 = CMP-0087176-1: MOSFET N-CH 100V 170MA SOT23-3; Manufacturer: Diodes Incorporated; Vgs_V: 20V; ChMode: False; AEC Qualified: No; SizeZ_mm: 1.1mm; Rdson45_ohm: 6
Q15 Q19 = CMP-0000962-2: MOSFET, N-CH, 100 V, 10 A, DQJ0008A (VSONP-8); Manufacturer: Texas Instruments; Alternate Manufacturer: None; U/M: EA; ChType: N; Value: 100V; Value2: 17 nC; QgTyp_nC: 17; Vgs_V: 20V; IdsMax_A: 10A; SizeAreaWB_mm2: 55.2; SizeArea_mm2: 29.4; SizeX_mm: 6; SizeY_mm: 4.9; SizeZ_mm: 1.1; AEC Category: Q101
R33 = CMP-0022204-4: RES, 20.0 k, 1%, 0.1 W, AEC-Q200 Grade 0, 0603; PartNumber: CRCW060320K0FKEA; Manufacturer: Vishay-Dale; Value: 20.0k; Res_ohm: 20k; Value_Code: 20k0; Power_W: 100mW; Value2: 0.1W; VDC_V: 75V; TempCo: 100 ppm/C; SizeArea_mm2: 1.28; SizeX_mm: 1.6; SizeY_mm: 0.8; SizeZ_mm: 1; EIA_Code: E96; AEC Category: Q200; AEC Qualified: Y; AEC Grade: 0
R34 R60 = CMP-0022254-4: RES, 27.4 k, 1%, 0.1 W, AEC-Q200 Grade 0, 0603; PartNumber: CRCW060327K4FKEA; Manufacturer: Vishay-Dale; Value: 27.4k; Value_Code: 27k4; Power_W: 100mW; Value2: 0.1W; VDC_V: 75V; TempCo: 100 ppm/C; EIA_Code: E96; SizeArea_mm2: 1.28; SizeX_mm: 1.6; SizeY_mm: 0.8; SizeZ_mm: 1; AEC Category: Q200; AEC Qualified: Y; AEC Grade: 0
R35 = CMP-0021998-4: RES, 10.0 k, 1%, 0.1 W, AEC-Q200 Grade 0, 0603; PartNumber: CRCW060310K0FKEA; Manufacturer: Vishay-Dale; Value: 10.0k; Res_ohm: 10k; Value_Code: 10k0; Power_W: 100mW; Value2: 0.1W; VDC_V: 75V; TempCo: 100 ppm/C; SizeArea_mm2: 1.28; SizeX_mm: 1.6; SizeY_mm: 0.8; SizeZ_mm: 1; EIA_Code: E96; AEC Category: Q200; AEC Qualified: Y; AEC Grade: 0
R36 R38 R39 R41 R61 R63 = CMP-0021990-4: RES, 100 k, 1%, 0.1 W, AEC-Q200 Grade 0, 0603; PartNumber: CRCW0603100KFKEA; Manufacturer: Vishay-Dale; Value: 100k; Power_W: 100mW; Value2: 0.1W; VDC_V: 75V; TempCo: 100 ppm/C; SizeArea_mm2: 1.28; SizeX_mm: 1.6; SizeY_mm: 0.8; SizeZ_mm: 1; EIA_Code: E96; AEC Category: Q200; AEC Qualified: Y; AEC Grade: 0
R37 R62 = CMP-0022040-4: RES, 137 k, 1%, 0.1 W, AEC-Q200 Grade 0, 0603; PartNumber: CRCW0603137KFKEA; Manufacturer: Vishay-Dale; Value: 137k; Power_W: 100mW; Value2: 0.1W; VDC_V: 75V; TempCo: 100 ppm/C; SizeArea_mm2: 1.28; SizeX_mm: 1.6; SizeY_mm: 0.8; SizeZ_mm: 1; EIA_Code: E96; AEC Category: Q200; AEC Qualified: Y; AEC Grade: 0
R40 = CMP-0022532-4: RES, 60.4 k, 1%, 0.1 W, AEC-Q200 Grade 0, 0603; Manufacturer: Vishay-Dale; CompType: Resistor; Value: 60.4k; Value_Code: 60k4; Power_W: 100mW; Value2: 0.1W; VDC_V: 75V; TempCo: 100 ppm/C; EIA_Code: E96; AEC Category: Q200; AEC Qualified: Y; AEC Grade: 0; SizeArea_mm2: 1.28; SizeX_mm: 1.6; SizeY_mm: 0.8; SizeZ_mm: 1
R42 R43 = CMP-0022133-4: RES, 1.78 k, 1%, 0.1 W, AEC-Q200 Grade 0, 0603; PartNumber: CRCW06031K78FKEA; Manufacturer: Vishay-Dale; Value: 1.78k; Value_Code: 1k78; Power_W: 100mW; Value2: 0.1W; VDC_V: 75V; TempCo: 100 ppm/C; SizeArea_mm2: 1.28; SizeX_mm: 1.6; SizeY_mm: 0.8; SizeZ_mm: 1; EIA_Code: E96; AEC Category: Q200; AEC Qualified: Y; AEC Grade: 0
R44 R65 = CMP-0016077-3: RES, 1.3 k, 5%, 0.75 W, AEC-Q200 Grade 0, 2010; Manufacturer: Vishay-Dale; Power_W: 750mW; TempCo: 200 ppm/C; Value_Code: 1k30; Value: 1.3k; EIA_Code: E24; SizeX_mm: 5; SizeY_mm: 2.5; SizeZ_mm: 1.66; Value2: 0.75W; SizeArea_mm2: 12.5; AEC Qualified: Y; VDC_V: 400V; AEC Grade: 0; AEC Category: Q200
R45 R50 = CMP-0022426-4: RES, 44.2 k, 1%, 0.1 W, AEC-Q200 Grade 0, 0603; PartNumber: CRCW060344K2FKEA; Manufacturer: Vishay-Dale; Value: 44.2k; Value_Code: 44k2; Power_W: 100mW; Value2: 0.1W; VDC_V: 75V; TempCo: 100 ppm/C; EIA_Code: E96; AEC Category: Q200; AEC Grade: 0; AEC Qualified: Y; SizeArea_mm2: 1.28; SizeX_mm: 1.6; SizeY_mm: 0.8; SizeZ_mm: 1
R46 R66 = CMP-0022447-4: RES, 49.9 k, 1%, 0.1 W, AEC-Q200 Grade 0, 0603; PartNumber: CRCW060349K9FKEA; Manufacturer: Vishay-Dale; Value: 49.9k; Value_Code: 49k9; Power_W: 100mW; Value2: 0.1W; VDC_V: 75V; TempCo: 100 ppm/C; EIA_Code: E96; AEC Category: Q200; AEC Qualified: Y; AEC Grade: 0; SizeArea_mm2: 1.28; SizeX_mm: 1.6; SizeY_mm: 0.8; SizeZ_mm: 1
R47 R67 = CMP-0021376-3: RES, 63.4, 1%, 0.125 W, AEC-Q200 Grade 0, 0805; PartNumber: CRCW080563R4FKEA; Manufacturer: Vishay-Dale; Value: 63.4; Value_Code: 63R4; Power_W: 125mW; Value2: 0.125W; VDC_V: 150V; TempCo: 100 ppm/C; EIA_Code: E96; AEC Category: Q200; AEC Grade: 0; AEC Qualified: Y; SizeArea_mm2: 2.5; SizeX_mm: 2; SizeY_mm: 1.25; SizeZ_mm: 1.45
R48 R68 = CMP-0021073-3: RES, 249, 1%, 0.125 W, AEC-Q200 Grade 0, 0805; Manufacturer: Vishay-Dale; Power_W: 125mW; TempCo: 100 ppm/C; Value_Code: 249R; Value: 249; EIA_Code: E96; SizeX_mm: 2; SizeY_mm: 1.25; SizeZ_mm: 1.45; Value2: 0.125W; SizeArea_mm2: 2.5; AEC Qualified: Y; VDC_V: 150V; AEC Category: Q200; AEC Grade: 0
R49 R69 = CMP-0022324-4: RES, 30.1 k, 1%, 0.1 W, AEC-Q200 Grade 0, 0603; PartNumber: CRCW060330K1FKEA; Manufacturer: Vishay-Dale; Value: 30.1k; Value_Code: 30k1; Power_W: 100mW; Value2: 0.1W; VDC_V: 75V; TempCo: 100 ppm/C; SizeArea_mm2: 1.28; SizeX_mm: 1.6; SizeY_mm: 0.8; SizeZ_mm: 1; EIA_Code: E96; AEC Category: Q200; AEC Qualified: Y; AEC Grade: 0
R51 R52 R54 = CMP-0021998-4: RES, 10.0 k, 1%, 0.1 W, AEC-Q200 Grade 0, 0603; PartNumber: CRCW060310K0FKEA; Manufacturer: Vishay-Dale; Value: 10.0k; Res_ohm: 10k; Value_Code: 10k0; Power_W: 100mW; Value2: 0.1W; VDC_V: 75V; TempCo: 100 ppm/C; EIA_Code: E96; AEC Category: Q200; AEC Grade: 0; AEC Qualified: Y; SizeArea_mm2: 1.28; SizeX_mm: 1.6; SizeY_mm: 0.8; SizeZ_mm: 1
R53 = CMP-0022109-5: RES, 1.00 k, 1%, 0.1 W, AEC-Q200 Grade 0, 0603; PartNumber: CRCW06031K00FKEA; Manufacturer: Vishay-Dale; Value: 1.00k; Res_ohm: 1k; Value_Code: 1k00; Power_W: 100mW; Value2: 0.1W; VDC_V: 75V; TempCo: 100 ppm/C; SizeArea_mm2: 1.28; SizeX_mm: 1.6; SizeY_mm: 0.8; SizeZ_mm: 1; EIA_Code: E96; AEC Category: Q200; AEC Qualified: Y; AEC Grade: 0
R55-R58 = CMP-0023050-5: RES, 35.7 k, 1%, 0.1 W, 0603; Manufacturer: Yageo; CompType: Resistor; Value: 35.7k; Value_Code: 35k7; Power_W: 100mW; Value2: 0.1W; VDC_V: 75V; TempCo: 100 ppm/C; EIA_Code: E96; AEC Category: Q200; AEC Qualified: N; SizeArea_mm2: 1.28; SizeX_mm: 1.6; SizeY_mm: 0.8; SizeZ_mm: 1; SizeAreaWB_mm2: 4.68
R59 = CMP-0021998-4: RES, 10.0 k, 1%, 0.1 W, AEC-Q200 Grade 0, 0603; Manufacturer: Vishay-Dale; Value: 10.0k; Res_ohm: 10k; Value_Code: 10k0; Power_W: 100mW; Value2: 0.1W; VDC_V: 75V; TempCo: 100 ppm/C; SizeArea_mm2: 1.28; SizeX_mm: 1.6; SizeY_mm: 0.8; SizeZ_mm: 1; EIA_Code: E96; AEC Category: Q200; AEC Qualified: Y; AEC Grade: 0
R64 = CMP-0022532-4: RES, 60.4 k, 1%, 0.1 W, AEC-Q200 Grade 0, 0603; Manufacturer: Vishay-Dale; Value: 60.4k; Value_Code: 60k4; Power_W: 100mW; Value2: 0.1W; VDC_V: 75V; TempCo: 100 ppm/C; EIA_Code: E96; AEC Category: Q200; AEC Qualified: Y; AEC Grade: 0; SizeArea_mm2: 1.28; SizeX_mm: 1.6; SizeY_mm: 0.8; SizeZ_mm: 1
U1 U7 = CMP-0013755-3: IEEE 802.3bt PoE High-Power PD Interface with Automatic MPS & Autoclass, RGW0020B (VQFN-20); Alternate PartNumber: TPS2372-3RGWT; Manufacturer: Texas Instruments; SizeArea_mm2: 25; SizeAreaWB_mm2: 49; SizeX_mm: 5; SizeZ_mm: 1; CompType: IC; AEC Category: Q200; AEC Qualified: N
U2-U6 = CMP-0006166-3: Optocoupler, 3.75 kV, 80-160% CTR, SMT; Manufacturer: Vishay-Semiconductor; CTR (Max): 160%; SizeAreaWB_mm2: 43.65; CTR (Min): 80%; SizeZ_mm: 2.3; SizeX_mm: 7; SizeY_mm: 2.85; SizeArea_mm2: 19.95; Voltage_Isolation_Vrms: 3.75kV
